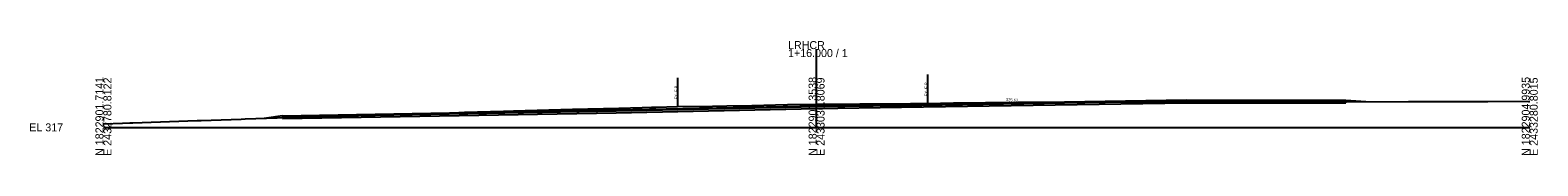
# Model space of a CAD drawing. Extents: x 2432865 to 2441203, y 1814550 to 1826842.
# Drawn here: x 2439604 to 2440132, y 1821809 to 1821849 of the extents above; entities that cross this region are included whole.
import ezdxf

# ---------------------------------------------------------------- set-up
doc = ezdxf.new("R2010")
doc.units = 0
for name, color, linetype in [('no plot', 7, 'Continuous'), ('X_TRANS_EOP', 7, 'Continuous'), ('X_TRANS_TX', 7, 'Continuous'), ('XS_CELL', 7, 'Continuous'), ('XS_P_FINISHED_GRADE', 7, 'Continuous'), ('XS_P_SUBGRADE_GRANULAR', 7, 'Continuous'), ('XS_P_SUBGRADE_PAVEMENT', 7, 'Continuous'), ('XS_X_GROUND', 7, 'Continuous')]:
    doc.layers.add(name, color=color, linetype=linetype)

msp = doc.modelspace()

# ---------------------------------------------------------------- linework, layer by layer
at = {"layer": 'X_TRANS_EOP'}
for p, q in [((2439918.18, 1821836.72), (2439918.18, 1821826.72)), ((2439830.56, 1821835.6), (2439830.56, 1821825.6))]:
    msp.add_line(p, q, dxfattribs=at)
at = {"layer": 'XS_CELL'}
for p, q in [((2439879.27, 1821818.22), (2439879.27, 1821845.67)), ((2439629.27, 1821818.22), (2439879.27, 1821818.22)), ((2439879.27, 1821818.22), (2440129.27, 1821818.22))]:
    msp.add_line(p, q, dxfattribs=at)
at = {"layer": 'XS_P_FINISHED_GRADE'}
for p, q in [((2440064.86, 1821827.74), (2440071.81, 1821827.25)), ((2439692.01, 1821822.25), (2439685.59, 1821821.37))]:
    msp.add_line(p, q, dxfattribs=at)
msp.add_lwpolyline([(2439692.01, 1821822.25), (2439809.01, 1821824.32), (2439879.27, 1821825.81), (2439909, 1821826.21), (2440009, 1821827.82), (2440064.86, 1821827.74)], dxfattribs=at)
at = {"layer": 'XS_P_SUBGRADE_GRANULAR'}
for points in [[(2439692.01, 1821821.29), (2439809.03, 1821823.36), (2439879.29, 1821824.85), (2439909.02, 1821825.25), (2440009.01, 1821826.86), (2440064.86, 1821826.78)], [(2440064.86, 1821826.78), (2440064.86, 1821827.74)], [(2439692.01, 1821822.25), (2439692.01, 1821821.29)]]:
    msp.add_lwpolyline(points, dxfattribs=at)
at = {"layer": 'XS_P_SUBGRADE_PAVEMENT'}
msp.add_lwpolyline([(2439692.02, 1821821.96), (2439809.02, 1821824.03), (2439879.28, 1821825.52), (2439909.01, 1821825.92), (2440009.01, 1821827.53), (2440064.86, 1821827.45)], dxfattribs=at)
at = {"layer": 'XS_X_GROUND'}
msp.add_lwpolyline([(2439629.27, 1821819.47), (2439635.94, 1821819.7), (2439638.56, 1821819.8), (2439639.56, 1821819.83), (2439662.17, 1821820.6), (2439663.56, 1821820.65), (2439677.59, 1821821.13), (2439678.9, 1821821.17), (2439701.44, 1821821.86), (2439703.89, 1821821.93), (2439726.12, 1821822.62), (2439728.88, 1821822.7), (2439750.79, 1821823.37), (2439753.87, 1821823.46), (2439755.8, 1821823.52), (2439769.47, 1821823.94), (2439772.98, 1821824.01), (2439793.75, 1821824.65), (2439809.92, 1821824.99), (2439818.16, 1821825.21), (2439821.4, 1821825.28), (2439822.9, 1821825.33), (2439830.56, 1821825.5), (2439842.77, 1821825.7), (2439847.86, 1821825.76), (2439856.53, 1821825.94), (2439869.13, 1821826.19), (2439879.27, 1821826.3), (2439894.45, 1821826.47), (2439908.24, 1821826.46), (2439912.19, 1821826.54), (2439918.18, 1821826.62), (2439927.31, 1821826.79), (2439949.69, 1821827), (2439950.54, 1821827.02), (2439951.43, 1821827.02), (2439975.57, 1821827.07), (2439976.2, 1821827.07), (2439999.95, 1821827.12), (2440000.61, 1821827.12), (2440024.16, 1821827.17), (2440025.69, 1821827.16), (2440038.41, 1821827.19), (2440039.58, 1821827.18), (2440061.85, 1821827.24), (2440064.59, 1821827.23), (2440086.8, 1821827.29), (2440089.59, 1821827.28), (2440111.77, 1821827.34), (2440114.59, 1821827.33), (2440129.27, 1821827.37)], dxfattribs=at)

# ---------------------------------------------------------------- texts
at = {"layer": 'no plot'}
msp.add_text('325.61', height=1, rotation=357.7094, dxfattribs=at).set_placement((2439945.66, 1821827.45))
at = {"layer": 'X_TRANS_TX'}
for p in [(2439830.56, 1821828), (2439918.18, 1821829.12)]:
    msp.add_text('EX. E.P.', height=1, rotation=90, dxfattribs=at).set_placement(p)
at = {"layer": 'XS_CELL'}
for s, p in [('LRHCR', (2439869.27, 1821845.67)), ('1+16.000 / 1', (2439869.27, 1821842.87)), ('EL 317', (2439603.27, 1821816.82))]:
    msp.add_text(s, height=2.8, dxfattribs=at).set_placement(p)
for s, p in [('N 1822901.7141', (2439629.27, 1821808.22)), ('E 2432780.8122', (2439632.07, 1821808.22)), ('N 1822903.3538', (2439879.27, 1821808.22)), ('E 2433030.8069', (2439882.07, 1821808.22)), ('N 1822904.9935', (2440129.27, 1821808.22)), ('E 2433280.8015', (2440132.07, 1821808.22))]:
    msp.add_text(s, height=2.8, rotation=90, dxfattribs=at).set_placement(p)

doc.saveas('drawing.dxf')
